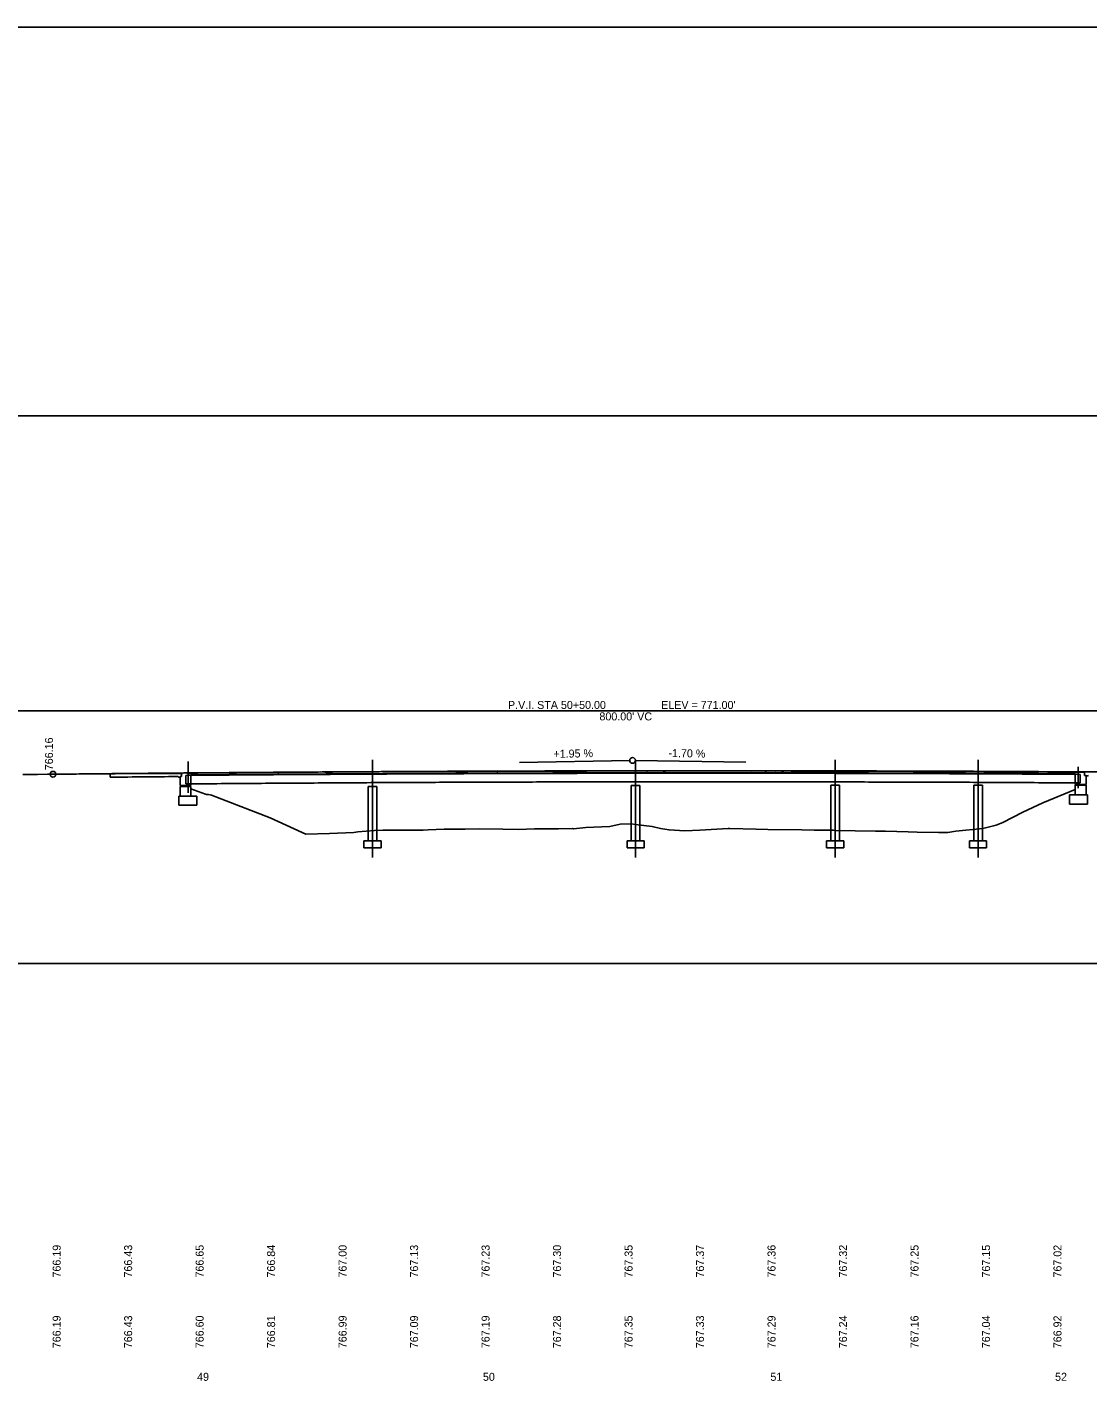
# Model space of a CAD drawing. Extents: x 40 to 3352, y -2509 to 347.
# Drawn here: x 290.7 to 661.7, y -126.3 to 347.3 of the extents above; entities that cross this region are included whole.
import ezdxf

# ---------------------------------------------------------------- set-up
doc = ezdxf.new("R2010")
doc.units = 0
for name, color, linetype in [('BR_P_Brg_Centerline', 7, 'Continuous'), ('BR_P_Gen_Approach_Slab', 7, 'Continuous'), ('BR_P_Slab_Object', 7, 'Continuous'), ('BR_X_Sub_Object', 7, 'Continuous'), ('Default', 7, 'Continuous'), ('GK_Cells', 7, 'Continuous'), ('PF_P_Grade_Line', 7, 'Continuous'), ('PF_P_Sta_Elev_Text', 7, 'Continuous'), ('PF_P_Text', 7, 'Continuous'), ('PF_X_Ground_Line', 7, 'Continuous'), ('PF_X_Text', 7, 'Continuous'), ('XS_X_Ground_Line', 7, 'Continuous')]:
    doc.layers.add(name, color=color, linetype=linetype)

msp = doc.modelspace()

# ---------------------------------------------------------------- linework, layer by layer
at = {"layer": 'BR_P_Brg_Centerline'}
for p, q in [((346.98, 90.31), (346.98, 79.43)), ((411.48, 90.94), (411.48, 56.73)), ((503.48, 90.94), (503.48, 56.73)), ((573.23, 90.94), (573.23, 56.73)), ((623.23, 90.94), (623.23, 56.73)), ((658.24, 88.53), (658.24, 81.04))]:
    msp.add_line(p, q, dxfattribs=at)
at = {"layer": 'BR_P_Gen_Approach_Slab'}
for p, q in [((319.73, 86.1), (319.73, 84.85)), ((344.73, 86.33), (344.73, 85.08)), ((660.49, 86.72), (660.49, 85.47)), ((660.49, 85.47), (660.99, 85.47)), ((660.99, 85.3), (661.49, 85.3)), ((661.49, 85.3), (661.81, 85.46)), ((343.73, 84.91), (343.42, 85.06)), ((344.23, 84.91), (343.73, 84.91)), ((344.73, 85.08), (344.23, 85.08))]:
    msp.add_line(p, q, dxfattribs=at)
msp.add_spline([(319.73, 84.85), (320.29, 84.86), (331.61, 84.96), (342.93, 85.06), (343.42, 85.06)], degree=3, dxfattribs=at)
at = {"layer": 'BR_P_Slab_Object'}
for p, q in [((347.99, 85.64), (347.99, 81.95)), ((657.23, 86.03), (657.23, 82.35)), ((660.99, 85.47), (660.99, 82.35)), ((344.23, 85.08), (344.23, 81.95)), ((344.23, 81.95), (347.99, 81.95)), ((657.23, 82.35), (660.99, 82.35))]:
    msp.add_line(p, q, dxfattribs=at)
at = {"layer": 'BR_X_Sub_Object'}
for p, q in [((346.23, 85.51), (346.23, 82.51)), ((658.99, 85.86), (658.99, 82.86)), ((344.23, 81.62), (347.99, 81.62)), ((344.23, 81.62), (344.23, 78.28)), ((347.99, 81.62), (347.99, 78.28)), ((409.98, 81.58), (409.98, 62.63)), ((409.98, 81.58), (412.99, 81.58)), ((412.99, 81.58), (412.99, 62.63)), ((501.98, 81.93), (501.98, 62.63)), ((501.98, 81.93), (504.99, 81.93)), ((504.99, 81.93), (504.99, 62.63)), ((571.73, 82.11), (571.73, 62.63)), ((571.73, 82.11), (574.74, 82.11)), ((574.74, 82.11), (574.74, 62.63)), ((621.73, 82.12), (621.73, 62.63)), ((621.73, 82.12), (624.74, 82.12)), ((624.74, 82.12), (624.74, 62.63)), ((657.23, 82.06), (657.23, 78.68)), ((657.23, 82.06), (660.99, 82.06)), ((660.99, 82.06), (660.99, 78.68)), ((343.73, 78.28), (343.73, 75.03)), ((343.73, 78.28), (349.99, 78.28)), ((349.99, 78.28), (349.99, 75.03)), ((655.23, 78.68), (655.23, 75.43)), ((655.23, 78.68), (661.49, 78.68)), ((661.49, 78.68), (661.49, 75.43)), ((343.73, 75.03), (349.99, 75.03)), ((655.23, 75.43), (661.49, 75.43)), ((408.48, 62.63), (408.48, 60.13)), ((408.48, 62.63), (414.49, 62.63)), ((414.49, 62.63), (414.49, 60.13)), ((500.48, 62.63), (500.48, 60.13)), ((500.48, 62.63), (506.49, 62.63)), ((506.49, 62.63), (506.49, 60.13)), ((570.23, 62.63), (570.23, 60.13)), ((570.23, 62.63), (576.24, 62.63)), ((576.24, 62.63), (576.24, 60.13)), ((620.23, 62.63), (620.23, 60.13)), ((620.23, 62.63), (626.24, 62.63)), ((626.24, 62.63), (626.24, 60.13)), ((408.48, 60.13), (414.49, 60.13)), ((500.48, 60.13), (506.49, 60.13)), ((570.23, 60.13), (576.24, 60.13)), ((620.23, 60.13), (626.24, 60.13))]:
    msp.add_line(p, q, dxfattribs=at)
for points in [[(346.23, 85.51), (354.25, 85.57), (365.57, 85.66), (376.89, 85.74), (388.21, 85.81), (399.53, 85.88), (410.85, 85.95), (422.17, 86), (433.49, 86.06), (444.81, 86.1), (456.13, 86.14), (467.45, 86.18), (478.77, 86.2), (490.09, 86.23), (501.41, 86.24), (512.73, 86.25), (524.05, 86.26), (535.37, 86.26), (546.69, 86.25), (558.01, 86.24), (569.33, 86.22), (580.65, 86.19), (591.97, 86.16), (603.29, 86.13), (614.61, 86.09), (625.93, 86.04), (637.25, 85.98), (648.57, 85.92), (658.99, 85.86)], [(346.23, 82.51), (354.25, 82.57), (365.57, 82.66), (376.89, 82.74), (388.21, 82.81), (399.53, 82.88), (410.85, 82.95), (422.17, 83), (433.49, 83.06), (444.81, 83.1), (456.13, 83.14), (467.45, 83.18), (478.77, 83.2), (490.09, 83.23), (501.41, 83.24), (512.73, 83.25), (524.05, 83.26), (535.37, 83.26), (546.69, 83.25), (558.01, 83.24), (569.33, 83.22), (580.65, 83.19), (591.97, 83.16), (603.29, 83.13), (614.61, 83.09), (625.93, 83.04), (637.25, 82.98), (648.57, 82.92), (658.99, 82.86)]]:
    msp.add_spline(points, degree=3, dxfattribs=at)
at = {"layer": 'Default'}
msp.add_lwpolyline([(88.85, 347.26), (976.56, 347.26), (976.56, 211.32), (88.85, 211.32)], close=True, dxfattribs=at)
at = {"layer": 'GK_Cells'}
msp.add_line((52.42, 19.74), (3352.42, 19.74), dxfattribs=at)
at = {"layer": 'PF_P_Grade_Line'}
for points in [[(299.73, 85.9), (308.97, 85.99), (320.29, 86.11), (331.61, 86.21), (342.93, 86.31), (354.25, 86.4), (365.57, 86.49), (376.89, 86.57), (388.21, 86.65), (399.53, 86.72), (410.85, 86.78), (422.17, 86.84), (433.49, 86.9), (444.81, 86.94), (456.13, 86.98), (467.45, 87.02), (478.77, 87.05), (490.09, 87.07), (501.41, 87.09), (512.73, 87.1), (524.05, 87.11), (535.37, 87.11), (546.69, 87.1), (558.01, 87.09), (569.33, 87.07), (580.65, 87.05), (591.97, 87.02), (603.29, 86.98), (614.61, 86.94), (625.93, 86.9), (637.25, 86.84), (648.57, 86.78), (659.89, 86.72), (671.21, 86.65), (682.53, 86.57), (693.85, 86.49), (705.17, 86.41), (705.49, 86.4)], [(347.99, 85.64), (354.25, 85.7), (365.57, 85.78), (376.89, 85.86), (388.21, 85.94), (399.53, 86.01), (410.85, 86.08), (422.17, 86.13), (433.49, 86.19), (444.81, 86.23), (456.13, 86.27), (467.45, 86.31), (478.77, 86.34), (490.09, 86.36), (501.41, 86.38), (512.73, 86.39), (524.05, 86.4), (535.37, 86.4), (546.69, 86.39), (558.01, 86.38), (569.33, 86.36), (580.65, 86.34), (591.97, 86.31), (603.29, 86.28), (614.61, 86.23), (625.93, 86.19), (637.25, 86.14), (648.57, 86.08), (657.23, 86.03)]]:
    msp.add_spline(points, degree=3, dxfattribs=at)
at = {"layer": 'PF_P_Text'}
for p, q in [((218.41, 108.13), (784.41, 108.13)), ((462.82, 89.97), (501.42, 90.72)), ((542.01, 90.07), (503.41, 90.72))]:
    msp.add_line(p, q, dxfattribs=at)
for centre in [(502.41, 90.74), (299.73, 85.9)]:
    msp.add_circle(centre, 1, dxfattribs=at)
at = {"layer": 'PF_X_Ground_Line'}
for points in [[(289.14, 85.8), (293.61, 85.84), (294.32, 85.84), (297.76, 85.89), (300.35, 85.92), (302.99, 85.94), (304.55, 85.94), (308.92, 85.98), (313.31, 86.02), (314.59, 86.04), (319.01, 86.05), (320.31, 86.06), (320.44, 86.06), (321.51, 86.08), (323.86, 86.14), (324.81, 86.15), (326.98, 86.17), (337.77, 86.17), (341.7, 86.16), (345.06, 86.21)], [(345.06, 86.21), (345.06, 86.21)], [(345.2, 86.31), (345.61, 86.33), (346.48, 86.3), (347.12, 86.32), (348.43, 86.32), (348.98, 86.32), (350.43, 86.32), (350.85, 86.33), (352.35, 86.34), (352.69, 86.34), (354.32, 86.35), (354.53, 86.35), (356.26, 86.36), (356.36, 86.37), (358.09, 86.37), (358.2, 86.37), (360.09, 86.38), (360.23, 86.38), (360.4, 86.38), (363.64, 86.42), (363.89, 86.43), (365.39, 86.45), (365.7, 86.45), (367.18, 86.46), (367.57, 86.47), (368.98, 86.48), (370.01, 86.49), (371.31, 86.5), (372.47, 86.52), (373.1, 86.52), (374.52, 86.54), (374.88, 86.54), (375.64, 86.55), (376.84, 86.55), (377.85, 86.55), (378.76, 86.56), (379.74, 86.57), (380.56, 86.58), (381.27, 86.59), (382.39, 86.59), (383.02, 86.6), (384.16, 86.61), (384.76, 86.61), (385.99, 86.62), (386.48, 86.63), (387.8, 86.64), (388.21, 86.64), (389.63, 86.65), (389.94, 86.66), (391.51, 86.66), (391.73, 86.66), (393.34, 86.68), (394.81, 86.67), (395.38, 86.67), (395.43, 86.67), (397.31, 86.67), (397.51, 86.67), (398.91, 86.69), (399.16, 86.69), (400.56, 86.71), (400.89, 86.71), (402.22, 86.73), (402.64, 86.73), (403.93, 86.74), (404.39, 86.74), (405.63, 86.75), (406.26, 86.75), (407.31, 86.77), (407.99, 86.77), (409.19, 86.77), (410.05, 86.77), (411.1, 86.77), (412.06, 86.77), (413.15, 86.78), (413.85, 86.79), (414.44, 86.8), (415.63, 86.8), (416.18, 86.8), (417.49, 86.81), (417.98, 86.81), (419.47, 86.81), (419.84, 86.81), (421.27, 86.82), (421.52, 86.83), (423.19, 86.83), (424.88, 86.83), (425.18, 86.84), (425.19, 86.84), (427.28, 86.83), (427.49, 86.83), (428.9, 86.84), (429.22, 86.84), (430.61, 86.85), (431.02, 86.85), (432.39, 86.86), (432.89, 86.86), (433.98, 86.88)], [(433.98, 86.88), (434.53, 86.88), (435.47, 86.9), (436.16, 86.9), (436.91, 86.9), (438.35, 86.88), (438.77, 86.88), (439.72, 86.88), (440.81, 86.88), (442.06, 86.89), (442.56, 86.9), (443.1, 86.9), (444.34, 86.91), (444.86, 86.91), (445.94, 86.93), (446.34, 86.93), (447.88, 86.93), (448.24, 86.93), (450.11, 86.93), (450.27, 86.93), (452.23, 86.93), (452.27, 86.93), (452.48, 86.93), (454.89, 86.91), (455.1, 86.91), (455.35, 86.91), (456.7, 86.93), (457.89, 86.94), (458.34, 86.94), (459.52, 86.96), (459.98, 86.96), (461.31, 86.96), (461.94, 86.96), (463.1, 86.97), (463.94, 86.97), (464.72, 86.98), (465.63, 86.98), (466.69, 86.95), (467.64, 86.95), (468.57, 86.96), (469.93, 86.97), (470.39, 86.97), (470.86, 86.98), (472.02, 86.99), (472.38, 87), (473.59, 87.01), (473.98, 87.01), (475.64, 87.01), (475.89, 87.01), (477.65, 87.02), (477.81, 87.02), (480.05, 87.01), (480.09, 87.01), (483.48, 86.98), (483.74, 86.98), (484.81, 87), (485.27, 87), (486.28, 87.02), (487.32, 87.04), (487.73, 87.04), (488.99, 87.05), (489.73, 87.05), (490.89, 87.06), (491.61, 87.06), (492.38, 87.07), (492.98, 87.09), (493.89, 87.09), (494.76, 87.09), (496.09, 87.06), (496.89, 87.06), (497.8, 87.07), (499.4, 87.07), (499.77, 87.08), (500.19, 87.09), (501.3, 87.1), (501.53, 87.1), (503.85, 87.06), (503.9, 87.05), (504.93, 87.07), (505.77, 87.05), (507.36, 87.02), (507.6, 87.01), (509.1, 87.09), (509.6, 87.09), (513.06, 87.02), (513.68, 87.02), (513.98, 87.02), (516.26, 87.12), (517.7, 87.12), (519.23, 87.09), (520.05, 87.06), (520.44, 87.05), (520.8, 87.05), (522.02, 87.06), (523.56, 87.07), (524.48, 87.08), (525.57, 87.08), (526.72, 87.07), (527.2, 87.07), (528.4, 87.08), (529.39, 87.07)], [(433.98, 86.88), (434.53, 86.88), (435.47, 86.9), (436.16, 86.9), (436.91, 86.9), (438.35, 86.88), (438.77, 86.88), (439.72, 86.88), (440.81, 86.88), (442.06, 86.89), (442.56, 86.9), (443.1, 86.9), (444.34, 86.91), (444.86, 86.91), (445.94, 86.93), (446.34, 86.93), (447.88, 86.93), (448.24, 86.93), (450.11, 86.93), (450.27, 86.93), (452.23, 86.93), (452.27, 86.93), (452.48, 86.93), (454.89, 86.91), (455.1, 86.91), (455.35, 86.91), (456.7, 86.93), (457.89, 86.94), (458.34, 86.94), (459.52, 86.96), (459.98, 86.96), (461.31, 86.96), (461.94, 86.96), (463.1, 86.97), (463.94, 86.97), (464.72, 86.98), (465.63, 86.98), (466.69, 86.95), (467.64, 86.95), (468.57, 86.96), (469.93, 86.97), (470.39, 86.97), (470.86, 86.98), (472.02, 86.99), (472.38, 87), (473.59, 87.01), (473.98, 87.01), (475.64, 87.01), (475.89, 87.01), (477.65, 87.02), (477.81, 87.02), (480.05, 87.01), (480.09, 87.01), (483.48, 86.98), (483.74, 86.98), (484.81, 87), (485.27, 87), (486.28, 87.02), (487.32, 87.04), (487.73, 87.04), (488.99, 87.05), (489.73, 87.05), (490.89, 87.06), (491.61, 87.06), (492.38, 87.07), (492.98, 87.09), (493.89, 87.09), (494.76, 87.09), (496.09, 87.06), (496.89, 87.06), (497.8, 87.07), (499.4, 87.07), (499.77, 87.08), (500.19, 87.09), (501.3, 87.1), (501.53, 87.1), (503.85, 87.06), (503.9, 87.05), (504.93, 87.07), (505.77, 87.05), (507.36, 87.02), (507.6, 87.01), (509.1, 87.09), (509.6, 87.09), (513.06, 87.02), (513.68, 87.02), (513.98, 87.02), (516.26, 87.12), (517.7, 87.12), (519.23, 87.09), (520.05, 87.06), (520.44, 87.05), (520.8, 87.05), (522.02, 87.06), (523.56, 87.07), (524.48, 87.08), (525.57, 87.08), (526.72, 87.07), (527.2, 87.07), (528.4, 87.08), (529.39, 87.07)], [(529.39, 87.07), (530.16, 87.09), (531.39, 87.08), (532.1, 87.07), (532.23, 87.06), (532.88, 87.06), (533.23, 87.07), (533.82, 87.03), (534.72, 87.06), (535.44, 87.07), (536.77, 87.05), (536.98, 87.05), (537.02, 87.05), (537.9, 87.06), (539.28, 87.06), (540.16, 87.06), (541.19, 87.06), (542.27, 87.05), (543.12, 87.04), (543.9, 87.02), (544.68, 87.04), (545.28, 87.05), (545.68, 87.05), (547.27, 87.05), (547.64, 87.05), (548.69, 87.01), (548.89, 87.01), (549.27, 87.01), (549.74, 87.03), (552.1, 87.03), (552.14, 87.03), (552.18, 87.03), (552.48, 87.02), (553.77, 87.03), (554.48, 87.02), (555.36, 87.02), (557.05, 87.03), (557.85, 87.02), (559.28, 87.02), (559.52, 87.02), (559.98, 87.02), (561.65, 87.01), (561.85, 87.01), (562.39, 87.01), (562.89, 87.01), (563.89, 87), (563.98, 86.98), (564.18, 86.99), (565.95, 87), (566.32, 87), (566.52, 87), (567.28, 87.01), (567.31, 87.01), (567.56, 87.01), (569.12, 86.99), (569.91, 86.99), (571.39, 86.99), (572.78, 86.99), (573.69, 86.99), (575.18, 86.98), (575.89, 86.98), (577.09, 86.99), (577.56, 86.97), (578.03, 86.97), (579.1, 86.97), (579.97, 86.97), (580.48, 86.97), (581.88, 86.97), (581.99, 86.97), (582.81, 86.96), (583.69, 86.97), (584.53, 86.96), (585.55, 86.95), (586.82, 86.95), (587.6, 86.94), (589.23, 86.94), (589.85, 86.94), (591.68, 86.94), (591.97, 86.93), (592.12, 86.93), (594.02, 86.93), (594.27, 86.93), (594.39, 86.93), (596.35, 86.92), (596.56, 86.92), (598.53, 86.92), (598.65, 86.91), (598.85, 86.92), (600.6, 86.9), (600.98, 86.9), (602.94, 86.89), (603.27, 86.89), (605.28, 86.89), (605.6, 86.89), (607.52, 86.88), (607.85, 86.88), (610.03, 86.88), (610.28, 86.88), (612.02, 86.86), (612.32, 86.86), (614.16, 86.85)], [(529.39, 87.07), (530.16, 87.09), (531.39, 87.08), (532.1, 87.07), (532.23, 87.06), (532.88, 87.06), (533.23, 87.07), (533.82, 87.03), (534.72, 87.06), (535.44, 87.07), (536.77, 87.05), (536.98, 87.05), (537.02, 87.05), (537.9, 87.06), (539.28, 87.06), (540.16, 87.06), (541.19, 87.06), (542.27, 87.05), (543.12, 87.04), (543.9, 87.02), (544.68, 87.04), (545.28, 87.05), (545.68, 87.05), (547.27, 87.05), (547.64, 87.05), (548.69, 87.01), (548.89, 87.01), (549.27, 87.01), (549.74, 87.03), (552.1, 87.03), (552.14, 87.03), (552.18, 87.03), (552.48, 87.02), (553.77, 87.03), (554.48, 87.02), (555.36, 87.02), (557.05, 87.03), (557.85, 87.02), (559.28, 87.02), (559.52, 87.02), (559.98, 87.02), (561.65, 87.01), (561.85, 87.01), (562.39, 87.01), (562.89, 87.01), (563.89, 87), (563.98, 86.98), (564.18, 86.99), (565.95, 87), (566.32, 87), (566.52, 87), (567.28, 87.01), (567.31, 87.01), (567.56, 87.01), (569.12, 86.99), (569.91, 86.99), (571.39, 86.99), (572.78, 86.99), (573.69, 86.99), (575.18, 86.98), (575.89, 86.98), (577.09, 86.99), (577.56, 86.97), (578.03, 86.97), (579.1, 86.97), (579.97, 86.97), (580.48, 86.97), (581.88, 86.97), (581.99, 86.97), (582.81, 86.96), (583.69, 86.97), (584.53, 86.96), (585.55, 86.95), (586.82, 86.95), (587.6, 86.94), (589.23, 86.94), (589.85, 86.94), (591.68, 86.94), (591.97, 86.93), (592.12, 86.93), (594.02, 86.93), (594.27, 86.93), (594.39, 86.93), (596.35, 86.92), (596.56, 86.92), (598.53, 86.92), (598.65, 86.91), (598.85, 86.92), (600.6, 86.9), (600.98, 86.9), (602.94, 86.89), (603.27, 86.89), (605.28, 86.89), (605.6, 86.89), (607.52, 86.88), (607.85, 86.88), (610.03, 86.88), (610.28, 86.88), (612.02, 86.86), (612.32, 86.86), (614.16, 86.85)], [(614.16, 86.85), (614.49, 86.85), (616.39, 86.84), (616.72, 86.83), (618.56, 86.82), (618.9, 86.82), (620.78, 86.81), (621.11, 86.81), (623.06, 86.8), (623.4, 86.8), (625.23, 86.79), (625.61, 86.79), (627.41, 86.78), (627.81, 86.77), (629.68, 86.77), (630.06, 86.76), (631.91, 86.75), (632.31, 86.75), (634.19, 86.75), (634.56, 86.74), (636.45, 86.74), (636.85, 86.73), (638.64, 86.72), (639.05, 86.72), (640.89, 86.71), (641.31, 86.71), (643.15, 86.7), (643.56, 86.7), (645.31, 86.68), (645.77, 86.68), (647.57, 86.67), (648.05, 86.67), (649.9, 86.66), (650.35, 86.66), (652.2, 86.66), (652.65, 86.66), (654.48, 86.65), (654.93, 86.65), (656.81, 86.64), (657.13, 86.64)], [(657.13, 86.64), (660.68, 86.65), (660.74, 86.67), (663.19, 86.7)]]:
    msp.add_lwpolyline(points, dxfattribs=at)
at = {"layer": 'XS_X_Ground_Line'}
msp.add_lwpolyline([(347.99, 80.75), (353.02, 78.89), (353.38, 78.84), (354.14, 78.8), (354.69, 78.7), (355.17, 78.53), (375.72, 70.63), (386.89, 65.53), (388.21, 64.98), (396.39, 65.13), (404.96, 65.54), (406.38, 65.76), (412.18, 66.18), (415.07, 66.39), (429.24, 66.37), (430.93, 66.42), (436.51, 66.65), (441.94, 66.68), (443.91, 66.69), (448.54, 66.77), (457.03, 66.69), (462.49, 66.51), (468.15, 66.83), (470.48, 66.79), (476.56, 66.83), (481.46, 66.86), (481.78, 66.84), (486.04, 67.31), (494.44, 67.57), (498.1, 68.39), (501.89, 68.55), (503.48, 68.36), (509.25, 67.67), (512.18, 66.96), (515.16, 66.43), (520.68, 66.09), (525.93, 66.3), (535.81, 66.91), (536.41, 66.89), (545.61, 66.65), (549.77, 66.59), (561.58, 66.45), (565.91, 66.39), (572.65, 66.28), (573.19, 66.27), (587.42, 66), (590.88, 65.93), (598.82, 65.72), (601.9, 65.66), (609.43, 65.54), (612.66, 65.5), (615.51, 65.97), (624.92, 66.87), (629.55, 68.08), (631.86, 69.02), (638.86, 72.61), (645.85, 75.9), (657.23, 80.61)], dxfattribs=at)

# ---------------------------------------------------------------- texts
at = {"layer": 'PF_P_Sta_Elev_Text'}
for s, p in [('49', (350.13, -126.29)), ('49', (350.13, -126.29)), ('50', (450.09, -126.29)), ('50', (450.09, -126.29)), ('51', (550.62, -126.29)), ('51', (550.62, -126.29)), ('52', (650.16, -126.29)), ('52', (650.16, -126.29))]:
    msp.add_text(s, height=2.8, dxfattribs=at).set_placement(p)
at = {"layer": 'PF_P_Text'}
for s, p in [('P.V.I. STA 50+50.00', (458.85, 108.73)), ("ELEV = 771.00'", (512.41, 108.73)), ("800.00' VC", (490.83, 104.73))]:
    msp.add_text(s, height=2.8, dxfattribs=at).set_placement(p)
for s, rotation, p in [('766.16', 90, (299.73, 87.3)), ('+1.95 %', 1.1171, (474.77, 91.6)), ('-1.70 %', 359.0261, (514.95, 91.93)), ('766.19', 90, (302.42, -90.16)), ('766.43', 90, (327.42, -90.16)), ('766.65', 90, (352.41, -90.16)), ('766.84', 90, (377.41, -90.16)), ('767.00', 90, (402.41, -90.16)), ('767.13', 90, (427.41, -90.16)), ('767.23', 90, (452.41, -90.16)), ('767.30', 90, (477.41, -90.16)), ('767.35', 90, (502.41, -90.16)), ('767.37', 90, (527.41, -90.16)), ('767.36', 90, (552.41, -90.16)), ('767.32', 90, (577.41, -90.16)), ('767.25', 90, (602.41, -90.16)), ('767.15', 90, (627.41, -90.16)), ('767.02', 90, (652.41, -90.16))]:
    msp.add_text(s, height=2.8, rotation=rotation, dxfattribs=at).set_placement(p)
at = {"layer": 'PF_X_Text'}
for s, p in [('766.19', (302.42, -114.89)), ('766.43', (327.42, -114.89)), ('766.60', (352.41, -114.89)), ('766.81', (377.41, -114.89)), ('766.99', (402.41, -114.89)), ('767.09', (427.41, -114.89)), ('767.19', (452.41, -114.89)), ('767.28', (477.41, -114.89)), ('767.35', (502.41, -114.89)), ('767.33', (527.41, -114.89)), ('767.29', (552.41, -114.89)), ('767.24', (577.41, -114.89)), ('767.16', (602.41, -114.89)), ('767.04', (627.41, -114.89)), ('766.92', (652.41, -114.89))]:
    msp.add_text(s, height=2.8, rotation=90, dxfattribs=at).set_placement(p)

doc.saveas('drawing.dxf')
